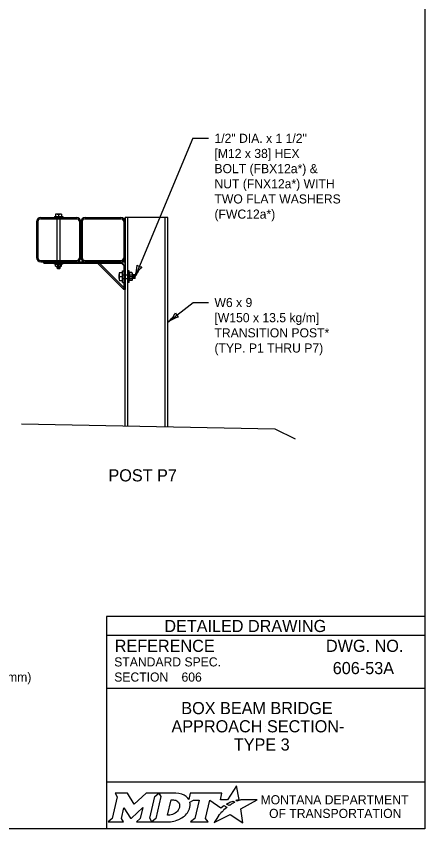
# Model space of a CAD drawing. Extents: x 49983 to 50021, y 49963.5 to 50011.4.
# Drawn here: x 50014.05 to 50016.75, y 49987.8 to 49993.16 of the extents above; entities that cross this region are included whole.
import ezdxf

# ---------------------------------------------------------------- set-up
doc = ezdxf.new("R2010")
doc.units = 0
for name, color, linetype in [('Default', 7, 'Continuous'), ('Level 1', 7, 'Continuous'), ('Level 10', 7, 'Continuous'), ('Level 2', 7, 'Continuous'), ('Level 3', 7, 'Continuous'), ('Level 5', 7, 'Continuous')]:
    doc.layers.add(name, color=color, linetype=linetype)

msp = doc.modelspace()

# ---------------------------------------------------------------- linework, layer by layer
at = {"layer": 'Default'}
for points in [[(50015.5126, 49987.9811), (50015.5023, 49987.9867), (50015.5139, 49987.9895), (50015.5255, 49987.9915), (50015.5081, 49988.0816), (50015.4486, 49987.9903), (50015.4013, 49987.9896), (50015.4116, 49988.0337), (50015.2024, 49988.0338), (50015.1923, 49987.9913), (50015.1865, 49987.9996)], [(50014.7056, 49988.0338), (50014.7197, 49988.0104), (50014.6862, 49987.8671), (50014.6605, 49987.8446), (50014.7621, 49987.8446), (50014.7486, 49987.8674), (50014.7648, 49987.9375), (50014.8085, 49987.8685), (50014.8138, 49987.8685), (50014.8889, 49987.938), (50014.8725, 49987.8669), (50014.8478, 49987.8449), (50014.9494, 49987.8449), (50014.9356, 49987.8682), (50014.9688, 49988.0106)], [(50014.9688, 49988.0106), (50014.9941, 49988.0338), (50014.9117, 49988.0338), (50014.8321, 49987.9608), (50014.7876, 49988.0335), (50014.7056, 49988.0338)], [(50015.1077, 49988.0338), (50014.9941, 49988.0338), (50015.0088, 49988.0109), (50014.9749, 49987.8671), (50014.9494, 49987.8449), (50015.06, 49987.8449)], [(50015.1317, 49987.9471), (50015.1305, 49987.939), (50015.1273, 49987.9297), (50015.1231, 49987.9215), (50015.1175, 49987.914), (50015.111, 49987.9071), (50015.1031, 49987.9008), (50015.0948, 49987.8961), (50015.0857, 49987.8922), (50015.0766, 49987.8899), (50015.0674, 49987.889), (50015.0515, 49987.889), (50015.0751, 49987.989), (50015.0911, 49987.989), (50015.0987, 49987.9884), (50015.1063, 49987.9865), (50015.1129, 49987.9835), (50015.119, 49987.9793), (50015.1238, 49987.9743), (50015.1275, 49987.9683), (50015.1302, 49987.9621), (50015.1318, 49987.9547), (50015.1318, 49987.9517), (50015.1317, 49987.9471)], [(50015.1991, 49987.9747), (50015.2237, 49987.9878), (50015.2606, 49987.9878), (50015.232, 49987.8673), (50015.2045, 49987.8446), (50015.3207, 49987.8446), (50015.3037, 49987.8675), (50015.3319, 49987.9877), (50015.4032, 49987.936), (50015.4243, 49987.9511), (50015.444, 49987.9402)], [(50015.3882, 49987.8843), (50015.3729, 49987.8599), (50015.3682, 49987.8524), (50015.3624, 49987.8438), (50015.3601, 49987.8395), (50015.4654, 49987.8926), (50015.5493, 49987.8375), (50015.5362, 49987.9302), (50015.6431, 49987.9886), (50015.5938, 49987.9894), (50015.5637, 49987.9898), (50015.5429, 49987.9901), (50015.5361, 49987.9886), (50015.5312, 49987.9874), (50015.5228, 49987.9851), (50015.5126, 49987.9811)], [(50015.4622, 49987.9535), (50015.4598, 49987.9518), (50015.4415, 49987.9614), (50015.4518, 49987.9671), (50015.4559, 49987.9693), (50015.4645, 49987.9733), (50015.4702, 49987.9759), (50015.4781, 49987.9789), (50015.4854, 49987.9816), (50015.4972, 49987.9742), (50015.4932, 49987.9721), (50015.4886, 49987.9696), (50015.4844, 49987.9674), (50015.4794, 49987.9645), (50015.4775, 49987.9634), (50015.4748, 49987.9618), (50015.4723, 49987.9604), (50015.47, 49987.9588), (50015.4674, 49987.957), (50015.4647, 49987.9552), (50015.4622, 49987.9535)], [(50015.4021, 49987.9004), (50015.4021, 49987.9004)], [(50015.1057, 49987.8522), (50015.1141, 49987.8548), (50015.1271, 49987.8602), (50015.1475, 49987.8712)]]:
    msp.add_lwpolyline(points, dxfattribs=at)
for centre, radius, start, end in [((50015.1308, 49987.9554), 0.0709, 339.5329, 15.8582), ((50015.0868, 49987.9727), 0.1183, 300.9103, 339.1383)]:
    msp.add_arc(centre, radius, start, end, dxfattribs=at)
for centre, major_axis, ratio, start_param, end_param in [((50015.1056, 49987.9864), (0.0834, -0.0037), 0.568097, 0.61298, 1.570796), ((50015.1612, 49987.9937), (0.0361, -0.0295), 0.469099, 1.225588, 1.570796), ((50015.4329, 49987.9305), (-0.0112, -0.0097), 0.021651, 3.157348, 6.283185), ((50015.3952, 49987.8923), (-0.00694, -0.00806), 0.008222, 0, 3.137361), ((50015.4119, 49987.9106), (-0.0098, -0.0102), 0.016458, 3.141593, 6.279097), ((50015.0603, 49987.9932), (0, 0.1484), 0.987302, 3.139398, 3.456847)]:
    msp.add_ellipse(centre, major_axis=major_axis, ratio=ratio, start_param=start_param, end_param=end_param, dxfattribs=at)
at = {"layer": 'Level 1'}
for p, q in [((50014.3136, 49991.8523), (50014.3136, 49991.8375)), ((50014.3235, 49991.8534), (50014.3432, 49991.8534)), ((50014.3333, 49991.8523), (50014.3333, 49991.8375)), ((50014.3531, 49991.8523), (50014.3531, 49991.8375)), ((50014.1869, 49991.8016), (50014.1869, 49991.5674)), ((50014.1961, 49991.8041), (50014.1961, 49991.5648)), ((50014.2137, 49991.8217), (50014.453, 49991.8217)), ((50014.2162, 49991.8309), (50014.4504, 49991.8309)), ((50014.3051, 49991.8375), (50014.3612, 49991.8375)), ((50014.3051, 49991.8375), (50014.3051, 49991.8309)), ((50014.3242, 49991.5472), (50014.3242, 49991.8217)), ((50014.3425, 49991.5472), (50014.3425, 49991.8217)), ((50014.3612, 49991.8375), (50014.3612, 49991.8309)), ((50014.4706, 49991.8041), (50014.4706, 49991.5648)), ((50014.4797, 49991.8016), (50014.4797, 49991.5674)), ((50014.4797, 49991.8016), (50014.4797, 49991.5674)), ((50014.4889, 49991.8041), (50014.4889, 49991.5648)), ((50014.5065, 49991.8217), (50014.7458, 49991.8217)), ((50014.509, 49991.8309), (50014.7433, 49991.8309)), ((50014.7634, 49991.8041), (50014.7634, 49991.5648)), ((50014.7726, 49991.8309), (50014.7726, 49991.5381)), ((50014.7726, 49991.6387), (50014.7726, 49991.8309)), ((50015.0548, 49991.8309), (50014.7726, 49991.8309)), ((50014.7726, 49990.4567), (50014.7726, 49991.8309)), ((50014.7906, 49990.4563), (50014.7906, 49991.8309)), ((50015.0368, 49991.7527), (50015.0368, 49991.8309)), ((50015.0368, 49990.4514), (50015.0368, 49991.8309)), ((50015.0548, 49990.451), (50015.0548, 49991.8309)), ((50014.7726, 49991.7348), (50014.7726, 49991.7348)), ((50015.0368, 49991.6387), (50015.0368, 49991.7171)), ((50014.2137, 49991.5472), (50014.453, 49991.5472)), ((50014.2162, 49991.5381), (50014.4797, 49991.5381)), ((50014.2357, 49991.5381), (50014.7726, 49991.5381)), ((50014.2357, 49991.5289), (50014.2357, 49991.5381)), ((50014.2357, 49991.5289), (50014.7488, 49991.5289)), ((50014.3055, 49991.5223), (50014.3055, 49991.5289)), ((50014.3615, 49991.5223), (50014.3615, 49991.5289)), ((50014.4797, 49991.5381), (50014.7726, 49991.5381)), ((50014.5065, 49991.5472), (50014.7458, 49991.5472)), ((50014.7634, 49991.3563), (50014.5909, 49991.5288)), ((50014.6037, 49991.5289), (50014.7634, 49991.3692)), ((50014.7488, 49991.5289), (50014.7634, 49991.5143)), ((50014.7726, 49991.5381), (50014.7726, 49991.3563)), ((50014.3615, 49991.5223), (50014.3055, 49991.5223)), ((50014.3136, 49991.5094), (50014.3136, 49991.5193)), ((50014.3432, 49991.5063), (50014.3235, 49991.5063)), ((50014.3242, 49991.4955), (50014.3242, 49991.5063)), ((50014.3425, 49991.4955), (50014.3242, 49991.4955)), ((50014.3242, 49991.4955), (50014.326, 49991.4937)), ((50014.326, 49991.4937), (50014.3407, 49991.4937)), ((50014.3268, 49991.5038), (50014.3397, 49991.5038)), ((50014.3268, 49991.502), (50014.3397, 49991.502)), ((50014.3268, 49991.5001), (50014.3397, 49991.5001)), ((50014.3268, 49991.4983), (50014.3397, 49991.4983)), ((50014.3333, 49991.5193), (50014.3333, 49991.5094)), ((50014.3425, 49991.4955), (50014.3407, 49991.4937)), ((50014.3425, 49991.4955), (50014.3425, 49991.5063)), ((50014.3531, 49991.5094), (50014.3531, 49991.5193)), ((50014.7546, 49991.4026), (50014.7546, 49991.4778)), ((50014.7546, 49991.4778), (50014.7634, 49991.4778)), ((50014.7634, 49991.5143), (50014.7634, 49991.3563)), ((50014.7994, 49991.4778), (50014.7906, 49991.4778)), ((50014.7994, 49991.4026), (50014.7994, 49991.4778)), ((50014.7331, 49991.4272), (50014.7331, 49991.4537)), ((50014.7347, 49991.4669), (50014.7546, 49991.4669)), ((50014.7347, 49991.4404), (50014.7546, 49991.4404)), ((50014.8168, 49991.4669), (50014.8035, 49991.4669)), ((50014.8035, 49991.4404), (50014.8168, 49991.4404)), ((50014.8209, 49991.4272), (50014.8209, 49991.4537)), ((50014.8354, 49991.4527), (50014.8209, 49991.4527)), ((50014.8354, 49991.4282), (50014.8209, 49991.4282)), ((50014.8243, 49991.4317), (50014.8243, 49991.449)), ((50014.8268, 49991.4317), (50014.8268, 49991.449)), ((50014.8292, 49991.4317), (50014.8292, 49991.449)), ((50014.8317, 49991.4317), (50014.8317, 49991.449)), ((50014.8354, 49991.4527), (50014.8354, 49991.4282)), ((50014.8354, 49991.4527), (50014.8379, 49991.4503)), ((50014.8354, 49991.4282), (50014.8379, 49991.4306)), ((50014.8379, 49991.4306), (50014.8379, 49991.4503)), ((50014.7347, 49991.4139), (50014.7546, 49991.4139)), ((50014.7546, 49991.4026), (50014.7634, 49991.4026)), ((50014.7994, 49991.4026), (50014.7906, 49991.4026)), ((50014.8168, 49991.4139), (50014.8035, 49991.4139)), ((50014.7726, 49991.3563), (50014.7634, 49991.3563)), ((50014.0893, 49990.4704), (50015.7603, 49990.4369)), ((50015.7603, 49990.4369), (50015.8943, 49990.3699))]:
    msp.add_line(p, q, dxfattribs=at)
msp.add_lwpolyline([(49999.3835, 49998.9992), (50016.7501, 49998.9992), (50016.7501, 49987.7988), (49999.3835, 49987.7988)], close=True, dxfattribs=at)
for centre, radius, start, end in [((50014.3235, 49991.812), 0.0415, 76.2307, 103.7693), ((50014.3432, 49991.812), 0.0415, 76.2307, 103.7693), ((50014.2162, 49991.8016), 0.0293, 90, 180), ((50014.2137, 49991.8041), 0.0176, 90, 180), ((50014.4504, 49991.8016), 0.0293, 0, 90), ((50014.453, 49991.8041), 0.0176, 0, 90), ((50014.509, 49991.8016), 0.0293, 90, 180), ((50014.5065, 49991.8041), 0.0176, 90, 180), ((50014.7433, 49991.8016), 0.0293, 0, 90), ((50014.7458, 49991.8041), 0.0176, 0, 90), ((50014.2162, 49991.5674), 0.0293, 180, 270), ((50014.2137, 49991.5648), 0.0176, 180, 270), ((50014.4504, 49991.5674), 0.0293, 270, 0), ((50014.453, 49991.5648), 0.0176, 270, 0), ((50014.509, 49991.5674), 0.0293, 180, 270), ((50014.5065, 49991.5648), 0.0176, 180, 270), ((50014.7433, 49991.5674), 0.0293, 270, 0), ((50014.7458, 49991.5648), 0.0176, 270, 0), ((50014.7488, 49991.5143), 0.0146, 0, 90), ((50014.3235, 49991.5048), 0.0175, 55.616, 124.384), ((50014.3235, 49991.5238), 0.0175, 235.616, 304.384), ((50014.3432, 49991.5048), 0.0175, 55.616, 124.384), ((50014.3432, 49991.5238), 0.0175, 235.616, 304.384), ((50014.7888, 49991.4537), 0.0557, 166.2307, 193.7693), ((50014.7888, 49991.4272), 0.0557, 166.2307, 193.7693), ((50014.8229, 49991.4537), 0.0235, 145.616, 214.384), ((50014.8229, 49991.4272), 0.0235, 145.616, 214.384), ((50014.7974, 49991.4537), 0.0235, 325.616, 34.384), ((50014.7974, 49991.4272), 0.0235, 325.616, 34.384)]:
    msp.add_arc(centre, radius, start, end, dxfattribs=at)
at = {"layer": 'Level 10'}
for p, q in [((50014.3242, 49991.8217), (50014.3242, 49991.8375)), ((50014.3425, 49991.8217), (50014.3425, 49991.8375)), ((50014.3242, 49991.5472), (50014.3242, 49991.5063)), ((50014.3425, 49991.5472), (50014.3425, 49991.5063)), ((50014.7546, 49991.4527), (50014.8209, 49991.4527)), ((50014.7546, 49991.4282), (50014.8209, 49991.4282))]:
    msp.add_line(p, q, dxfattribs=at)
at = {"layer": 'Level 3'}
for p, q in [((50015.2194, 49992.3529), (50014.8379, 49991.4404)), ((50015.2194, 49992.3529), (50015.3219, 49992.3529)), ((50015.0548, 49991.141), (50015.2219, 49991.2698)), ((50015.2219, 49991.2698), (50015.3219, 49991.2698))]:
    msp.add_line(p, q, dxfattribs=at)
for centre, radius, start, end in [((50014.6187, 49991.5196), 0.233, 340.1341, 359.3839), ((50015.0393, 49991.3463), 0.2223, 134.7628, 154.9463), ((50014.8873, 49991.5587), 0.0548, 229.4456, 265.1679), ((50014.9036, 49991.3182), 0.233, 310.4646, 329.7145), ((50015.1832, 49990.9595), 0.2223, 105.0933, 125.2768), ((50015.1563, 49991.2193), 0.0548, 199.7761, 235.4985)]:
    msp.add_arc(centre, radius, start, end, dxfattribs=at)
at = {"layer": 'Level 5'}
for p, q in [((50016.7501, 49989.1988), (50014.6501, 49989.1988)), ((50014.6501, 49989.1988), (50014.6501, 49987.7988)), ((50016.7501, 49989.0738), (50014.6501, 49989.0738)), ((50016.3862, 49988.8587), (50016.3862, 49988.8587)), ((50015.1444, 49988.7993), (50015.1444, 49988.7993)), ((50016.7501, 49988.7238), (50014.6501, 49988.7238)), ((50015.7001, 49988.4747), (50015.7001, 49988.4747)), ((50016.7501, 49988.1057), (50014.6501, 49988.1057))]:
    msp.add_line(p, q, dxfattribs=at)

# ---------------------------------------------------------------- texts
at = {"layer": 'Default'}
for s, p in [('MONTANA DEPARTMENT', (50015.6663, 49987.96)), ('OF TRANSPORTATION', (50015.7225, 49987.87))]:
    msp.add_text(s, height=0.06, rotation=360, dxfattribs=at).set_placement(p)
at = {"layer": 'Level 1'}
for s, p in [('BOX BEAM BRIDGE', (50015.1432, 49988.5546)), ('APPROACH SECTION-', (50015.0784, 49988.4346)), ('TYPE 3', (50015.4898, 49988.3146))]:
    msp.add_text(s, height=0.08, dxfattribs=at).set_placement(p)
at = {"layer": 'Level 2'}
for s, height, p in [('1/2" DIA. x 1 1/2"', 0.06, (50015.3619, 49992.3229)), ('[M12 x 38] HEX', 0.06, (50015.3619, 49992.2229)), ('BOLT (FBX12a*) &', 0.06, (50015.3619, 49992.1229)), ('NUT (FNX12a*) WITH', 0.06, (50015.3619, 49992.0229)), ('TWO FLAT WASHERS', 0.06, (50015.3619, 49991.9229)), ('(FWC12a*) ', 0.06, (50015.3619, 49991.8229)), ('W6 x 9 ', 0.06, (50015.3619, 49991.2398)), ('[W150 x 13.5 kg/m]', 0.06, (50015.3619, 49991.1398)), ('TRANSITION POST* ', 0.06, (50015.3619, 49991.0398)), ('(TYP. P1 THRU P7)', 0.06, (50015.3619, 49990.9398)), ('POST P7', 0.08, (50014.6622, 49990.0898)), ('606-53A', 0.08, (50016.1428, 49988.8187)), ('METRIC AND ARE IN MILLMETERS (mm)', 0.06, (50012.62, 49988.7694)), ('606', 0.06, (50015.1444, 49988.7693))]:
    msp.add_text(s, height=height, dxfattribs=at).set_placement(p)
at = {"layer": 'Level 5'}
for s, height, p in [('DETAILED DRAWING', 0.0799, (50015.0311, 49989.0963)), ('REFERENCE', 0.08, (50014.7037, 49988.9654)), ('DWG. NO.', 0.08, (50016.0979, 49988.9654)), ('STANDARD SPEC.', 0.06, (50014.7004, 49988.8694)), ('SECTION', 0.06, (50014.7004, 49988.7694))]:
    msp.add_text(s, height=height, dxfattribs=at).set_placement(p)

doc.saveas('drawing.dxf')
